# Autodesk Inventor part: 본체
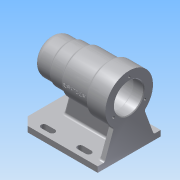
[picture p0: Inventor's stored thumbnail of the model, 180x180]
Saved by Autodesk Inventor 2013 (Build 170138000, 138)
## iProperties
Created: 2017-09
Part Number: 본체
Material: 알루미늄 6061
Document SubType Name: Modeling
Designer: Administrator
Density: 2.71 g/cm^3
Mass: 703.104 g
Surface Area: 714.776 cm^2
Volume: 259.448 cm^3
Author: Administrator
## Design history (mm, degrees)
sketch "스케치3"
  geometry: L1 (-56, 0)-(56, 0); L2 (-56, 0)-(-56, 25); L3 (-56, 25)-(-31, 25); L4 (-31, 25)-(-31, 27); L5 (-31, 27)-(-11, 27); L6 (-11, 27)-(-11, 30); L7 (-11, 30)-(28, 30); L8 (28, 30)-(28, 34); L9 (28, 34)-(56, 34); L10 (56, 34)-(56, 0); 2 further points
  constraints: 20 end point, 5 parallel, 4 perpendicular, 1 coincident, 1 horizontal, 1 midpoint
  dimensions: "d0" = 112 distance of L1.start L1.end; "d2" = 50 diameter of L3 L1; "d3" = 54 diameter of L5 L1; "d4" = 60 diameter of L7 L1; "d5" = 68 diameter of L9 L1; "d6" = 25 distance of L2.end L3.end; "d8" = 45 distance between parallel lines of L6 L2; "d9" = 84 distance between parallel lines of L8 L2
revolve "회전1" sketch "스케치3" stored, may be unused: angle "d10" = 90 deg
node "작업 평면1"
sketch "스케치4"
  geometry: L1 (56, -45)-(-56, -45); L2 (-56, -45)-(-56, 45); L3 (-56, 45)-(56, 45); L4 (56, 45)-(56, -45); 3 further points
  constraints: 8 end point, 2 midpoint, 2 parallel, 1 horizontal, 1 horizontal alignment, 1 perpendicular, 1 vertical alignment
  dimensions: "d12" = 112 distance of L2.end L3.end; "d14" = 90 distance of L1.end L2.end
extrude "돌출1" join sketch "스케치4" distance "d15" = 8; taper "d16" = 0 deg
sketch "스케치5"
  geometry: L1 (90, 0)-(0, 0) reference; L2 (90, 0)-(90, 8) reference; L3 (0, 8)-(90, 8) reference; L4 (0, 0)-(0, 8) reference; L5 (23.1, 43.992)-(10, 8); L6 (66.9, 43.992)-(80, 8); A1 r 34 centre (45, 70) between (23.1, 43.992) and (66.9, 43.992) reference; 1 further point
  constraints: 4 end point, 2 point on circle, 2 point on line
  dimensions: "d17" = 10 distance from line of L4 L5.end; "d18" = 10 distance from line of L2 L6.end; "d19" = 110 deg angle of L3 L5; "d20" = 110 deg angle of L3 L6 (= d19)
extrude "돌출2" join sketch "스케치5" distance "d21" = 8; taper "d22" = 0 deg
sketch "스케치6"
  geometry: L1 (56, -70)-(-56, -70) reference; L2 (56, -70)-(56, -62) reference; L3 (-56, -62)-(56, -62) reference; L4 (-56, -70)-(-56, -62) reference; L5 (-11, -27)-(-11, 27) reference; L6 (-31, -27)-(-31, 27) reference; L7 (-34, -62)-(-24.622, -27); L8 (-31, -27)-(-11, -27) reference; L9 (48, -26.008)-(48, -62) reference; L10 (-11, -30)-(28, -30) reference; L11 (28, -30)-(28, 30) reference; L12 (-11, -30)-(-11, 30) reference; L13 (48, -26.008)-(56, -26.008) reference; L14 (56, -26.008)-(56, -26.008) reference; L15 (56, -26.008)-(48, -26.008) reference; L16 (48, -26.008)-(48, -26.008) reference; L17 (28, -34)-(28, 34) reference; L18 (28, -34)-(48, -34) reference; 1 further point
  constraints: 2 end point, 2 point on line
  dimensions: "d23" = 22 distance from line of L7.start L4; "d24" = 105 deg angle of L3 L7
feature "리브1" sketch "스케치6" dims "d25" = 1, "d26" = 8, "d27" = 0, "d28" = 0, "d29" = 1, "d30" = 1
sketch "스케치7"
  geometry: C1 r 21 at (45, 70); 1 further point
  constraints: 1 centre point, 1 coincident
  dimensions: "d31" = 42 diameter of C1
extrude "돌출3" cut sketch "스케치7" distance "d33" = 15; taper "d34" = 0 deg
sketch "스케치8"
  geometry: C1 r 24 at (0, 0); 1 further point
  constraints: 1 centre point, 1 coincident
  dimensions: "d35" = 48 diameter of C1
extrude "돌출4" cut sketch "스케치8" distance "d37" = 54; taper "d38" = 0 deg
sketch "스케치9"
  geometry: C1 r 21 at (0, 0); 1 further point
  constraints: 1 centre point, 1 coincident
  dimensions: "d39" = 42 diameter of C1
extrude "돌출5" cut sketch "스케치9" distance "d41" = 12; taper "d42" = 0 deg
sketch "스케치10"
  geometry: C1 r 17.5 at (0, 0); 1 further point
  constraints: 1 centre point, 1 coincident
  dimensions: "d43" = 35 diameter of C1
extrude "돌출6" cut sketch "스케치10" distance "d45" = 18; taper "d46" = 0 deg
hole "구멍1" diameter "d49" = 21; stored, may be unused: countersink angle "d53" = 90 deg, drill point angle "d55" = 0 deg; dims "d47" = 10, "d48" = 10, "d50" = 6, "d51" = 32, "d52" = 4, "d54" = 7
sketch "스케치11" dims "d60" = 52
  geometry: 3 further points
  constraints: 2 vertical alignment, 1 coincident, 2 other
hole "구멍2" sketch "스케치11" at (45, 96) diameter "d62" = 3.242; stored, may be unused: countersink angle "d66" = 90 deg, drill point angle "d68" = 118 deg; dims "d63" = 8, "d64" = 32, "d65" = 4, "d67" = 11
node "작업 평면2"
sketch "스케치12"
  geometry: L1 (47.5, -26.008)-(47.5, -26.008) reference; L2 (47.5, -26.008)-(39.5, -26.008) reference; L3 (39.5, -26.008)-(39.5, -33.764) reference; L4 (39.5, -33.764)-(19.5, -33.764) reference; L5 (19.5, -33.764)-(19.5, -33.764) reference; L6 (19.5, -33.764)-(39.5, -33.764) reference; L7 (39.5, -33.764)-(39.5, -26.008) reference; L8 (39.5, -26.008)-(47.5, -26.008) reference; L9 (47.5, -26.008)-(47.5, 34) reference; 2 further points
  constraints: 1 horizontal alignment, 1 other
  dimensions: "d72" = 48 distance from line of L9 point (-0.5, 0)
feature "엠보싱1" sketch "스케치12" dims "d73" = 0.5, "d74" = 0
sketch "스케치13"
  geometry: L1 (56, 45)-(56, -45) reference; L2 (56, -45)-(-56, -45) reference; L3 (-56, -45)-(-56, 45) reference; L4 (-56, 45)-(56, 45) reference; L5 (20, -30)-(32, -30); L6 (32, -38)-(20, -38); L7 (-32, -30)-(-20, -30); L8 (-20, -38)-(-32, -38); L9 (-56, 0)-(56, 0); L10 (-20, 38)-(-32, 38); L11 (-32, 30)-(-20, 30); L12 (32, 38)-(20, 38); L13 (20, 30)-(32, 30); A1 r 4 centre (32, -34) between (32, -38) and (32, -30); A2 r 4 centre (20, -34) between (20, -30) and (20, -38); A3 r 4 centre (-20, -34) between (-20, -38) and (-20, -30); A4 r 4 centre (-32, -34) between (-32, -30) and (-32, -38); A5 r 4 centre (-32, 34) between (-32, 38) and (-32, 30); A6 r 4 centre (-20, 34) between (-20, 30) and (-20, 38); A7 r 4 centre (20, 34) between (20, 38) and (20, 30); A8 r 4 centre (32, 34) between (32, 30) and (32, 38); 1 further point
  constraints: 18 end point, 16 point on circle, 12 symmetric about line, 8 centre point, 8 tangent, 3 parallel, 2 midpoint, 1 horizontal alignment, 4 other
  dimensions: "d75" = 4 radius of A2; "d77" = 12 distance of A1.centre A2.centre; "d78" = 34 vertical distance of A2.centre point (0, 0); "d79" = 24 distance from line of L1 A1.centre; "d80" = 4 radius of A4; "d81" = 12 distance of A3.centre A4.centre; "d82" = 40 distance of A2.centre A3.centre; "d83" = 24 distance from line of L3 A4.centre
extrude "돌출7" cut sketch "스케치13" stored distance "d84" = 18; taper "d85" = 0 deg
chamfer "모따기1" distance "d86" = 12; stored, may be unused: second distance "d87" = 2, angle "d88" = 45 deg
fillet "모깎기1" dims "d89" = 3
fillet "모깎기2" dims "d90" = 3
chamfer "모따기2" distance "d91" = 1; stored, may be unused: second distance "d92" = 2, angle "d93" = 45 deg
fillet "모깎기3" dims "d94" = 3
fillet "모깎기4" dims "d95" = 3
fillet "모깎기5" dims "d96" = 3
fillet "모깎기6" dims "d97" = 9
fillet "모깎기7" dims "d98" = 3
fillet "모깎기8" dims "d99" = 0.3
node "솔리드1"
pattern_circular "원형 패턴1" dims angle "d70" = 360 deg
node "투영된 루프1"
node "투영된 루프2"
node "투영된 루프3"
node "투영된 루프4"
node "투영된 루프5"
node "투영된 루프6"
node "투영된 루프7"
node "투영된 루프8"
other parameters: "d56" = 0.5, "d57" = 2, "d58" = 0
